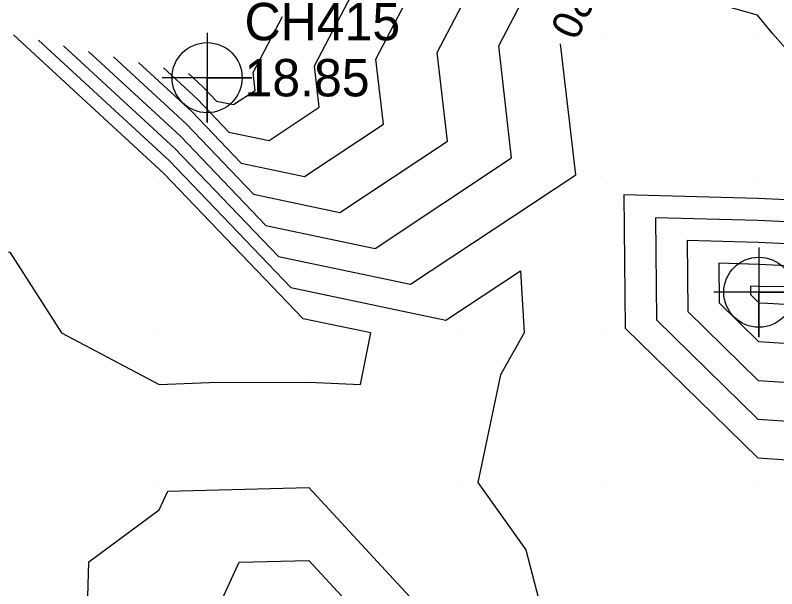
# Model space of a CAD drawing. Extents: x 2531902 to 2533249, y 715219 to 716099.
# Drawn here: x 2532750.4 to 2532801.3, y 715672.9 to 715711.2 of the extents above; entities that cross this region are included whole.
import ezdxf

# ---------------------------------------------------------------- set-up
doc = ezdxf.new("R2010")
doc.units = 0
for name, color, linetype in [('DTM Contours Major', 7, 'Continuous'), ('DTM Contours Major Text', 7, 'Continuous'), ('DTM Contours Minor', 7, 'Continuous'), ('Exist DTM QL2 LIDAR Elevation Point', 7, 'Continuous'), ('Exist DTM Regular Point CELL', 7, 'Continuous'), ('Exist DTM Regular Point Cogo Elevation', 7, 'Continuous'), ('Exist DTM Regular Point Cogo Number', 7, 'Continuous')]:
    doc.layers.add(name, color=color, linetype=linetype)

msp = doc.modelspace()

# ---------------------------------------------------------------- linework, layer by layer
at = {"layer": 'DTM Contours Major'}
for points in [[(2532761.946, 715707.348), (2532762.919, 715706.45), (2532763.821, 715705.509), (2532764.974, 715705.267), (2532766.414, 715706.221), (2532766.277, 715707.406), (2532768.246, 715711.17)], [(2532753.593, 715709.202), (2532761.051, 715702.322), (2532767.964, 715695.11), (2532776.801, 715693.25), (2532787.844, 715700.569), (2532786.834, 715709.326)], [(2532838.339, 715680.326), (2532829.347, 715688.533), (2532826.742, 715690.602), (2532819.021, 715698.211), (2532811.077, 715698.659), (2532808.104, 715698.607), (2532800.012, 715698.999), (2532791.063, 715699.233), (2532791.151, 715690.31), (2532800.011, 715681.635), (2532809.202, 715681.024), (2532810.45, 715680.953), (2532819.089, 715682.829), (2532821.288, 715680.501), (2532822.549, 715679.15)], [(2532763.194, 715670), (2532765.335, 715674.665), (2532770, 715674.787), (2532773.838, 715670.628)]]:
    msp.add_lwpolyline(points, dxfattribs=at)
at = {"layer": 'DTM Contours Minor'}
for points in [[(2532755.264, 715708.831), (2532761.425, 715703.148), (2532767.136, 715697.19), (2532774.435, 715695.654), (2532783.558, 715701.699), (2532782.693, 715709.201), (2532788.149, 715719.635), (2532793.35, 715727.325), (2532797.374, 715738.318), (2532800.952, 715745.193), (2532800.467, 715751.14)], [(2532756.934, 715708.46), (2532761.798, 715703.973), (2532766.307, 715699.27), (2532772.07, 715698.057), (2532779.272, 715702.83), (2532778.589, 715708.752), (2532787.11, 715725.047), (2532790.657, 715730.291), (2532793.401, 715737.789), (2532795.841, 715742.478), (2532795.511, 715746.534)], [(2532758.605, 715708.089), (2532762.172, 715704.799), (2532765.478, 715701.35), (2532769.705, 715700.46), (2532774.986, 715703.96), (2532774.485, 715708.303), (2532786.07, 715730.458), (2532787.964, 715733.258), (2532789.429, 715737.26), (2532790.731, 715739.763), (2532790.555, 715741.928)], [(2532808.721, 715701.279), (2532801.023, 715710), (2532800, 715711.26), (2532793.185, 715713.185), (2532798.736, 715721.392), (2532805.319, 715739.376)], [(2532760.276, 715707.718), (2532762.546, 715705.625), (2532764.65, 715703.43), (2532767.339, 715702.863), (2532770.7, 715705.091), (2532770.381, 715707.855), (2532785.031, 715735.869), (2532785.27, 715736.224), (2532785.456, 715736.731), (2532785.621, 715737.048), (2532785.599, 715737.322)], [(2532738.341, 715721.659), (2532739.945, 715719.993), (2532740, 715713.334), (2532741.631, 715710), (2532741.228, 715708.772), (2532740, 715708.658), (2532738.401, 715701.599), (2532738.808, 715700), (2532740, 715695.61), (2532744.341, 715695.659), (2532750, 715695.407), (2532753.468, 715690), (2532760, 715686.54), (2532763.327, 715686.673), (2532770, 715686.712), (2532773.454, 715686.546), (2532774.137, 715690), (2532769.621, 715690.95), (2532760.304, 715700.671), (2532750.252, 715709.944)], [(2532751.922, 715709.573), (2532760.677, 715701.497), (2532768.793, 715693.03), (2532779.166, 715690.847), (2532784.149, 715694.149), (2532784.391, 715690), (2532782.809, 715687.191), (2532781.293, 715680), (2532784.508, 715675.492), (2532785.937, 715670), (2532790, 715666.551), (2532793.131, 715666.869), (2532798.585, 715670), (2532799.711, 715670.289), (2532800, 715670.677), (2532800.412, 715670.412), (2532810, 715676.04)], [(2532836.249, 715680.736), (2532828.872, 715687.468), (2532824.377, 715691.038), (2532818.347, 715696.981), (2532812.144, 715697.33), (2532806.226, 715697.228), (2532800.03, 715697.528), (2532793.177, 715697.707), (2532793.245, 715690.874), (2532800.029, 715684.231), (2532807.067, 715683.763), (2532811.654, 715683.503), (2532818.401, 715684.969), (2532822.261, 715680.879), (2532829.061, 715673.594), (2532834.895, 715674.842), (2532836.249, 715680.736)], [(2532834.159, 715681.145), (2532828.398, 715686.403), (2532822.012, 715691.475), (2532817.674, 715695.751), (2532813.21, 715696.002), (2532804.349, 715695.848), (2532800.048, 715696.057), (2532795.292, 715696.181), (2532795.338, 715691.439), (2532800.047, 715686.828), (2532804.932, 715686.503), (2532812.858, 715686.054), (2532817.712, 715687.108), (2532823.235, 715681.257), (2532828.545, 715675.568), (2532833.101, 715676.543), (2532834.159, 715681.145)], [(2532832.069, 715681.555), (2532827.924, 715685.339), (2532819.647, 715691.912), (2532817, 715694.52), (2532814.277, 715694.674), (2532802.471, 715694.469), (2532800.066, 715694.586), (2532797.406, 715694.655), (2532797.432, 715692.003), (2532800.065, 715689.424), (2532802.797, 715689.242), (2532814.062, 715688.604), (2532817.024, 715689.247), (2532824.209, 715681.636), (2532828.03, 715677.542), (2532831.308, 715678.243), (2532832.069, 715681.555)], [(2532829.979, 715681.965), (2532827.449, 715684.274), (2532817.282, 715692.348), (2532816.327, 715693.29), (2532815.343, 715693.345), (2532800.593, 715693.09), (2532800.084, 715693.115), (2532799.52, 715693.129), (2532799.525, 715692.567), (2532800.083, 715692.02), (2532800.663, 715691.982), (2532815.266, 715691.154), (2532816.335, 715691.386), (2532825.182, 715682.014), (2532827.514, 715679.516), (2532829.514, 715679.944), (2532829.979, 715681.965)], [(2532744.197, 715658.124), (2532750.53, 715659.332), (2532755.197, 715660), (2532755.661, 715664.339), (2532755.149, 715670), (2532755.302, 715674.698), (2532760, 715678.168), (2532760.576, 715679.424), (2532770, 715679.67), (2532778.925, 715670), (2532770, 715660.689), (2532767.866, 715662.134), (2532767.499, 715660), (2532769.538, 715659.779), (2532769.938, 715659.616), (2532770.263, 715659.746), (2532779.564, 715658.636), (2532789.133, 715659.483), (2532789.891, 715659.35), (2532799.291, 715659.255), (2532800.311, 715659.539), (2532809.625, 715658.849)]]:
    msp.add_lwpolyline(points, dxfattribs=at)
at = {"layer": 'Exist DTM QL2 LIDAR Elevation Point'}
for p, q in [((2532790, 715710), (2532790, 715710)), ((2532800, 715710), (2532800, 715710)), ((2532760, 715700), (2532760, 715700)), ((2532790, 715700), (2532790, 715700)), ((2532800, 715700), (2532800, 715700)), ((2532760, 715690), (2532760, 715690)), ((2532770, 715690), (2532770, 715690)), ((2532780, 715690), (2532780, 715690)), ((2532790, 715690), (2532790, 715690)), ((2532760, 715680), (2532760, 715680)), ((2532770, 715680), (2532770, 715680)), ((2532780, 715680), (2532780, 715680)), ((2532790, 715680), (2532790, 715680)), ((2532800, 715680), (2532800, 715680))]:
    msp.add_line(p, q, dxfattribs=at)
at = {"layer": 'Exist DTM Regular Point CELL'}
for points in [[(2532763.2, 715710.069), (2532763.2, 715704.069), (2532763.2, 715707.069), (2532766.2, 715707.069), (2532760.2, 715707.069)], [(2532800.088, 715695.719), (2532800.088, 715689.719), (2532800.088, 715692.719), (2532803.088, 715692.719), (2532797.088, 715692.719)]]:
    msp.add_lwpolyline(points, dxfattribs=at)
for centre in [(2532763.2, 715707.069), (2532800.088, 715692.719)]:
    msp.add_circle(centre, 2.344, dxfattribs=at)

# ---------------------------------------------------------------- texts
at = {"layer": 'DTM Contours Major Text'}
msp.add_text('20', height=2, rotation=245.0554, dxfattribs=at).set_placement((2532787.353, 715713.033))
at = {"layer": 'Exist DTM Regular Point Cogo Elevation'}
msp.add_text('18.85', height=2.5, dxfattribs=at).set_placement((2532765.7, 715705.819))
at = {"layer": 'Exist DTM Regular Point Cogo Number'}
msp.add_text('CH415', height=2.5, dxfattribs=at).set_placement((2532765.7, 715709.569))

doc.saveas('drawing.dxf')
